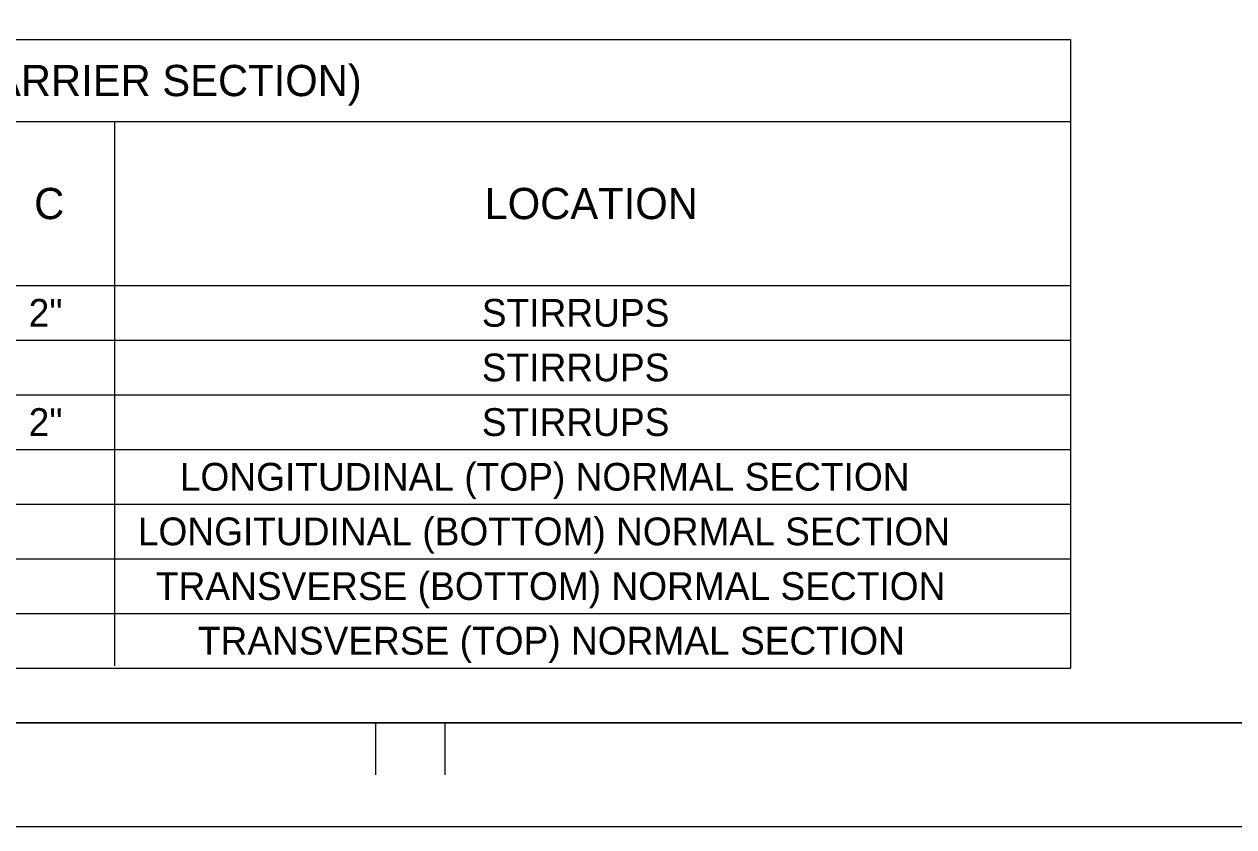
# Model space of a CAD drawing. Extents: x 499883 to 500983, y 499104 to 499764.
# Drawn here: x 500394.2 to 500568.6, y 499103.6 to 499219.3 of the extents above; entities that cross this region are included whole.
import ezdxf

# ---------------------------------------------------------------- set-up
doc = ezdxf.new("R2010")
doc.units = 0
for name, color, linetype in [('1', 7, 'Continuous'), ('41', 7, 'Continuous'), ('5', 7, 'Continuous')]:
    doc.layers.add(name, color=color, linetype=linetype)

msp = doc.modelspace()

# ---------------------------------------------------------------- linework, layer by layer
at = {"layer": '1'}
for p, q in [((499989.94, 499118.64), (500979.94, 499118.64)), ((500444.94, 499111.14), (500444.94, 499118.64)), ((500454.94, 499111.14), (500454.94, 499118.64)), ((500982.94, 499103.64), (499934.77, 499103.64))]:
    msp.add_line(p, q, dxfattribs=at)
at = {"layer": '41'}
for points in [[(499934.77, 499763.64), (500982.94, 499763.64), (500982.94, 499103.64), (499934.77, 499103.64)], [(499989.94, 499748.64), (500979.94, 499748.64), (500979.94, 499118.64), (499989.94, 499118.64)]]:
    msp.add_lwpolyline(points, close=True, dxfattribs=at)
at = {"layer": '5'}
for p, q in [((500174.98, 499217.06), (500545.06, 499217.06)), ((500545.06, 499217.06), (500545.06, 499126.51)), ((500174.98, 499205.25), (500545.06, 499205.25)), ((500407.26, 499205.25), (500407.26, 499126.84)), ((500174.98, 499181.63), (500545.06, 499181.63)), ((500174.98, 499173.76), (500545.06, 499173.76)), ((500174.98, 499165.88), (500545.06, 499165.88)), ((500174.98, 499158.01), (500545.06, 499158.01)), ((500174.98, 499150.13), (500545.06, 499150.13)), ((500174.98, 499142.26), (500545.06, 499142.26)), ((500174.98, 499134.39), (500545.06, 499134.39)), ((500174.98, 499126.51), (500545.06, 499126.51))]:
    msp.add_line(p, q, dxfattribs=at)

# ---------------------------------------------------------------- texts
for s, height, p in [('REINFORCEMENT STEEL LIST (EACH BARRIER SECTION)', 4.5, (500276.06, 499208.91)), ('C', 4.5, (500395.67, 499191.19)), ('LOCATION', 4.5, (500460.6, 499191.19)), ('2"', 4, (500394.88, 499175.69)), ('STIRRUPS', 4, (500460.21, 499175.69)), ('STIRRUPS', 4, (500460.21, 499167.82)), ('2"', 4, (500394.88, 499159.95)), ('STIRRUPS', 4, (500460.21, 499159.95)), ('LONGITUDINAL (TOP) NORMAL SECTION', 4, (500416.67, 499152.07)), ('LONGITUDINAL (BOTTOM) NORMAL SECTION', 4, (500410.62, 499144.2)), ('TRANSVERSE (BOTTOM) NORMAL SECTION', 4, (500413.22, 499136.32)), ('TRANSVERSE (TOP) NORMAL SECTION', 4, (500419.27, 499128.45))]:
    msp.add_text(s, height=height, dxfattribs=at).set_placement(p)

doc.saveas('drawing.dxf')
